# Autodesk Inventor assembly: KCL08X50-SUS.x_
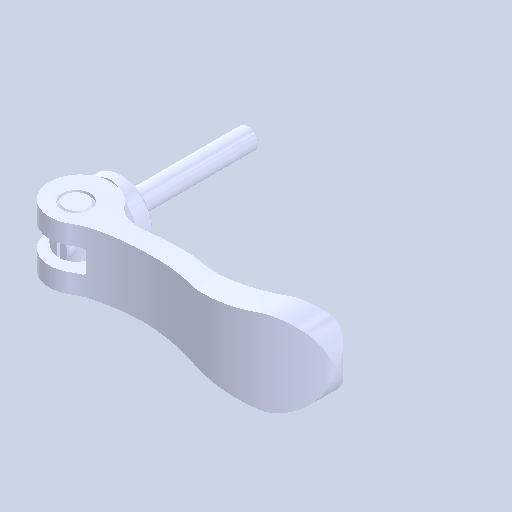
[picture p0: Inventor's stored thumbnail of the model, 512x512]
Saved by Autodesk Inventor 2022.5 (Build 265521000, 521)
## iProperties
Created: 2024-08
Part Number: KCL08X50-SUS.x_
Document SubType Name: Assembly
Designer: ImaoCorp
Author: ImaoCorp
Sending System: SOLIDWORKS 2022-2022290
MC: AMD64
MC_MODEL: Intel64 Family 6 Model 60 Stepping 3, GenuineIntel
OS: Windows_NT
FRU: Parasolid Version 33.1, build 260,  4-25-2022
FORMAT: text
GUISE: transmit
KEY: FILEKCL08X50-SUS.x_t
DATE: Thu Aug 29 10:50:46 2024
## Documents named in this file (5)
- Y:\5.更新分\2024年対応\1001_KCL\データ\kcl08x50-sus\KCL08X50-SUS.x_.iam
- Y:\5.更新分\2024年対応\1001_KCL\データ\kcl08x50-sus\KCL08X50-SUS_01.ipt
- Y:\5.更新分\2024年対応\1001_KCL\データ\kcl08x50-sus\KCL08X50-SUS_02.ipt
- Y:\5.更新分\2024年対応\1001_KCL\データ\kcl08x50-sus\KCL08X50-SUS_03.ipt
- Y:\5.更新分\2024年対応\1001_KCL\データ\kcl08x50-sus\KCL08X50-SUS_04.ipt
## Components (4 placed, 4 different names)
1. KCL08X50-SUS_01
2. KCL08X50-SUS_02
3. KCL08X50-SUS_03
4. KCL08X50-SUS_04
